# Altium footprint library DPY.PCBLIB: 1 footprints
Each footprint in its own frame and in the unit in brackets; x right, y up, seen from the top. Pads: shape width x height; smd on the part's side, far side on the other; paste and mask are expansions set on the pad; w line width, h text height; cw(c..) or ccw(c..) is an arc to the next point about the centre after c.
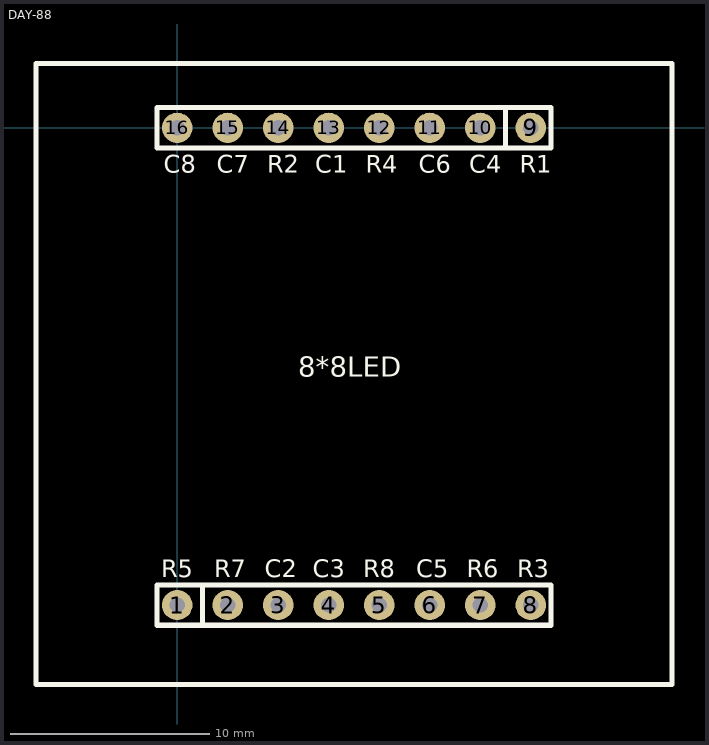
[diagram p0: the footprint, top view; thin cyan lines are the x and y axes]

## DAY-88 [mil]
height 330
pads (16):
  round 60 hole 30 paste+0: 1(0,-945) 2(100,-945) 3(200,-945) 4(300,-945) 5(400,-945) 6(500,-945) 7(600,-945) 8(700,-945) 9(700,0) 10(600,0) 11(500,0) 12(400,0) 13(300,0) 14(200,0) 15(100,0) 16(0,0)
Top Overlay:
  lines w10: 50,-985 50,-905 ; 650,-40 650,40 ; -280,-1102.5 980,-1102.5 980,127.5 -280,127.5 -280,-1102.5 ; -40,-985 -40,-905 740,-905 740,-985 -40,-985 ; -40,-40 -40,40 740,40 740,-40 -40,-40
  text "C8" at -27,-89.5 h35
  text "C7" at 78,-89.5 h35
  text "R2" at 178,-89.5 h35
  text "C1" at 273,-89.5 h35
  text "R4" at 373,-89.5 h35
  text "C6" at 478,-89.5 h35
  text "C4" at 578,-89.5 h35
  text "R1" at 678,-89.5 h35
  text "R3" at 673,-889.5 h35
  text "R6" at 573,-889.5 h35
  text "C5" at 473,-889.5 h35
  text "R8" at 368,-889.5 h35
  text "C3" at 268,-889.5 h35
  text "C2" at 173,-889.5 h35
  text "R7" at 73,-889.5 h35
  text "R5" at -32,-889.5 h35
  text "8*8LED" at 240,-492.5 h40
